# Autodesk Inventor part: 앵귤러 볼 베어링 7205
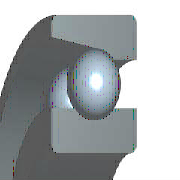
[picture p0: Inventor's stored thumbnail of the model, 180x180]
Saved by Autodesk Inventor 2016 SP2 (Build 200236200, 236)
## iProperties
Created: 2012-02
Part Number: 앵귤러 볼 베어링 7205
Material: 강철, 연강
Description: 앵귤러 콘택트 볼 베어링
Document SubType Name: Modeling
Standard: KS B 2024
Designer: mduedu
Standards Organization: KS
Language: ko-KR
Size Designation: 7205 - 25 x 52 x 15
Categories: <MemberInstance><Categories><Category DisplayName="샤프트 부품" InternalName="7f7aeb1f-a693-4053-b835-cee3144e0d98" Mnemonic="SHFT"><Category DisplayName="베어링" Inter
Density: 1 g/cm^3
Appearance: 노란색
IsCustomPart: 1
Author: mduedu
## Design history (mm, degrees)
sketch "스케치" dims "d1" = 7.02 (= -0.26 x WD + 0.26 x BD)
  geometry: L1 (3.99, 19.25)-(11.01, 19.25); L2 (7.5, 22.76)-(7.5, 15.74); L3 (0, 16.901)-(4.892, 16.901); L4 (0, 12.5)-(15, 12.5); L5 (8.11, 22.707)-(0, 24.137); L6 (15, 16.901)-(15, 12.5); L7 (15, 16.901)-(10.108, 16.901); L8 (15, 21.599)-(10.108, 21.599); L9 (15, 21.599)-(15, 26); L10 (0, 26)-(15, 26); L11 (-2.4, 0)-(14.4, 0) reference; L12 (0, -1.44)-(0, 8.99) reference; 1 further point
  constraints: 20 end point, 4 point on line, 3 symmetric about line, 2 midpoint, 2 parallel, 1 perpendicular, 14 other
  dimensions: "d0" = 10 deg angle of L8 L5; "d11" = 25 diameter of L4 L11 (= WD); "d12" = 52 diameter of L10 L11 (= BD); "d13" = 15 distance between parallel lines of L6 L12 (= KB); "d14" = 33.802 diameter of L7 L11 (= 0.326 x BD + 0.674 x WD)
revolve "본체" stored, may be unused: angle "d6" = 90 deg
revolve "볼" stored, may be unused: angle "d8" = 90 deg
pattern_circular "IDS_ARRAYBALL[SIMPL:T]" dims angle "d4" = 360 deg
body "Solid1"
fillet "모깎기1" dims "d2" = 1 (= KRS)
other parameters: "WD" = 25 [user parameter; used in 5 equation terms], "BD" = 52 [user parameter; used in 5 equation terms], "KB" = 15 [user parameter; used in 1 equation term], "KRS" = 1 [user parameter; used in 1 equation term], "d5" = 0, "d7" = 0, "d9" = 0, "d15" = 0, "d16" = 0, "BC0" = 1.02e+07 [user parameter], "BBA" = 30 deg [user parameter], "BC" = 1.56e+07 [user parameter], "KR1S" = 0.6 [user parameter], "BR" = 26 (= 0.5 x BD) [user parameter], "WR" = 12.5 (= 0.5 x WD) [user parameter]
